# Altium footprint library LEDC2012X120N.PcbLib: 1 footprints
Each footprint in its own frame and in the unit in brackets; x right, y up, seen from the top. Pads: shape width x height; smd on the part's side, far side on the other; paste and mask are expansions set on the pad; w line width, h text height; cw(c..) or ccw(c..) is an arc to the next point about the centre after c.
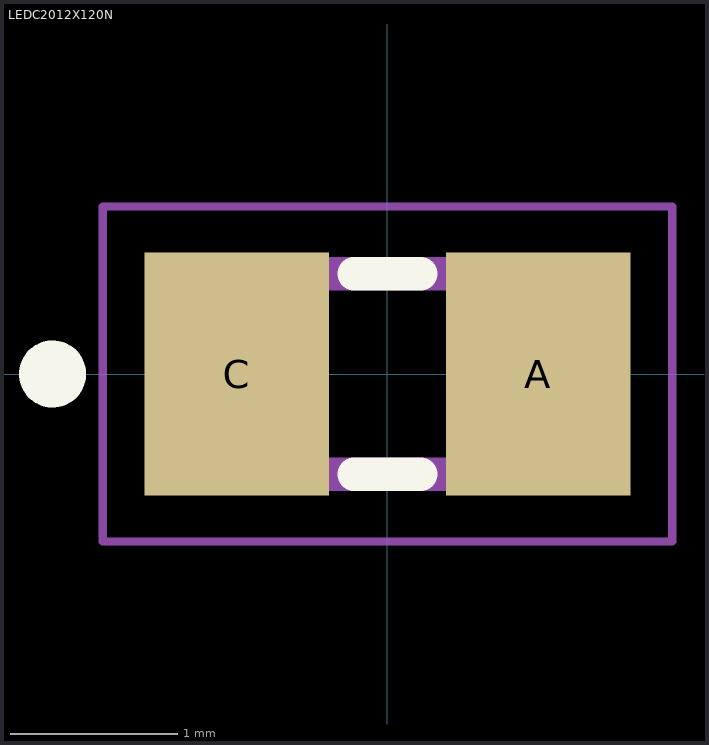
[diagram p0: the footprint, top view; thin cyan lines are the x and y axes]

## LEDC2012X120N [mm]
pads (2):
  rect 1.1x1.45 smd: A(0.9,0) C(-0.9,0)
Top Overlay:
  circle w0.2: c-2,0 r0.1
  lines w0.2: -0.2,-0.6 0.2,-0.6 ; -0.2,0.6 0.2,0.6
Mechanical 13:
  region: 1,-0.6 0.5,-0.6 0.5,0.6 1,0.6
  region: -0.5,-0.6 -1,-0.6 -1,0.6 -0.5,0.6
  lines w0.2: -1,-0.6 -1,0.6 1,0.6 1,-0.6 -1,-0.6
Mechanical 15:
  lines w0.05: -1.7,-1 -1.7,1 1.7,1 1.7,-1 -1.7,-1
3D body "step_temp.STEP": height 0.9, standoff 0, extent -1,-0.65 1,0.65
